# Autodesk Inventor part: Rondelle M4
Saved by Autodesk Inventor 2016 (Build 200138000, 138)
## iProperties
Created: 2013-10
Part Number: Rondelle M4
Material: Générique
Document SubType Name: Modeling
Designer: Bruno
Density: 1 g/cm^3
Appearance: Par défaut
Author: Bruno
Sending System: SolidWorks 2013
Last Author: christophe
Last Saved: 2014-02-15
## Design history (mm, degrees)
feature "Révolution1"
node "Solide1"
